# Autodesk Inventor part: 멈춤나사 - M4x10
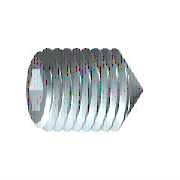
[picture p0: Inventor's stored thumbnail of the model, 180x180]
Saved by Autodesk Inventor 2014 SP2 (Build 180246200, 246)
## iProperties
Created: 2012-02
Part Number: 멈춤나사 - M4x10
Material: 강철, 연강
Description: 6각 소켓 머리 없는 멈춤 나사
Document SubType Name: Modeling
Standard: KS B 1028
Designer: mduedu
Standards Organization: KS
Language: ko-KR
Size Designation: 원추점 M4x10
Categories: <MemberInstance><Categories><Category DisplayName="조임쇠" InternalName="e4da775c-781d-43d5-af7c-5136215cf5a6" Mnemonic="FSTN"><Category DisplayName="볼트" InternalN
Density: 7.86 g/cm^3
Mass: 0.792069 g
Surface Area: 1.48192 cm^2
Volume: 0.100772 cm^3
Appearance: 강철
Author: mduedu
IsCustomPart: 1
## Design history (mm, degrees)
sketch "스케치1"
  geometry: L1 (0, 0)-(6.833, 0); L2 (10, 1.155)-(10, 2); L3 (10, 2)-(0, 2); L4 (10, 1.155)-(7.5, 1.155); L5 (7.5, 1.155)-(6.833, 0); L6 (0, -0.4)-(0, 2.4) reference; L7 (0, 2)-(0, 0)
  constraints: 13 end point, 3 parallel, 1 collinear, 1 perpendicular, 1 point on line
  dimensions: "d0" = 2.5 distance of L2.start L4.end (= INTI); "d1" = 60 deg angle of L5 L1; "d2" = 4 diameter of L3 L1 (= NND); "d3" = 2.3094 diameter of L4 L1 (= 1.1547 x SW); "d5" = 10 distance from line of L2 L3.end (= NLG)
revolve "본체" sketch "스케치1" stored, may be unused: angle "d6" = 90 deg
sketch "스케치2"
  geometry: L1 (-0.577, 1)-(0.577, 1); L2 (0.577, 1)-(1.155, 0); L3 (1.155, 0)-(0.577, -1); L4 (0.577, -1)-(-0.577, -1); L5 (-0.577, -1)-(-1.155, 0); L6 (-1.155, 0)-(-0.577, 1); 3 further points
  constraints: 12 end point, 1 coincident, 1 horizontal, 13 other
extrude "슬롯" join sketch "스케치2" taper "d7" = 0 deg; stored distance "d21" = 10
workaxis "Work Axis1"
workplane "Work Plane1"
sketch "스케치4"
  geometry: L1 (-5, 0.2)-(-3.2, 2) reference; L2 (-5, -0.2)-(-3.2, -2) reference; L3 (-3.2, 2)-(-5.2, 0); L4 (-3.2, -2)-(-5.2, 0); 2 further points
  constraints: 4 end point, 2 collinear, 1 coincident
body "Solid1"
feature "스레드" dims "d12" = 10 (= NLG), "d13" = 0
chamfer "모따기1" distance "d8" = 1.8 (computed from NND, SPD, FAWI); stored, may be unused: angle "d9" = 45 deg (= FAWI), second distance "d34" = 1.8 (computed from NND, SPD, FAWI)
chamfer "모따기2" distance "d10" = 0.42941 (= -0.5 x GD1 + 0.5 x NND); stored, may be unused: angle "d11" = 45 deg (= FAWI), second distance "d35" = 0.42941 (= -0.5 x GD1 + 0.5 x NND)
other parameters: "NND" = 4 [user parameter; used in 5 equation terms], "NLG" = 10 [user parameter; used in 2 equation terms], "INTI" = 2.5 [user parameter; used in 1 equation term], "FAWI" = 45 deg [user parameter; used in 4 equation terms], "SW" = 2 [user parameter; used in 2 equation terms], "GD1" = 3.14117 (= THREADDIA - 1.2269 x PTC) [user parameter; used in 2 equation terms], "d4" = 0, "FAWI1" = 45 deg [user parameter], "SPD" = 0.4 [user parameter; used in 2 equation terms], "d36" = 0, "d37" = 0, "GUL" = 0.42941 (= 0.61345 x PTC) [user parameter], "TPU" = 14.28571 (computed from PTC) [user parameter], "TOA" = 30 deg [user parameter], "THREADDIA" = 4 [user parameter; used in 1 equation term], "PTC" = 0.7 [user parameter; used in 4 equation terms], "GAL" = 0.42941 (= 0.61345 x PTC) [user parameter], "E0" = 2.31 (= 1.155 x SW) [user parameter]
